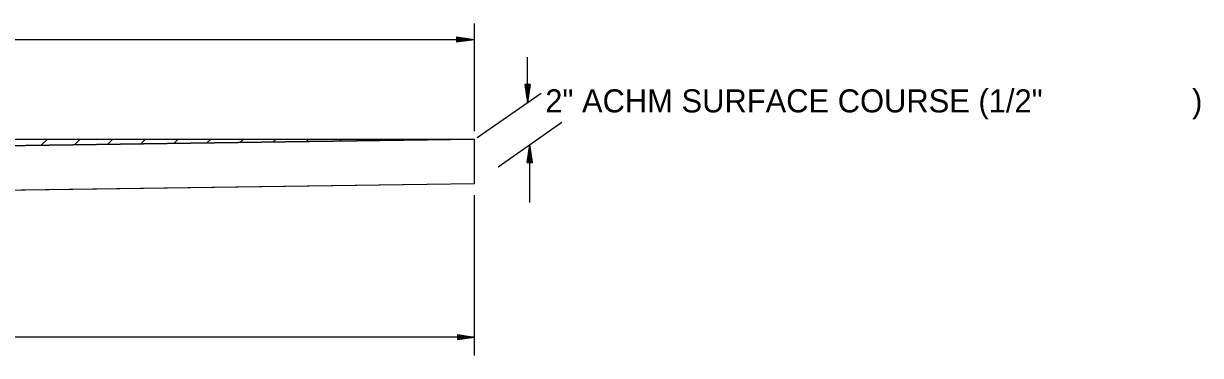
# Model space of a CAD drawing. Extents: x 1929624 to 1935547, y 596315 to 605721.
# Drawn here: x 1935241 to 1935546.7, y 602932.7 to 603019.1 of the extents above; entities that cross this region are included whole.
import ezdxf

# ---------------------------------------------------------------- set-up
doc = ezdxf.new("R2010")
doc.units = 0
doc.layers.add('Default', color=7, linetype='Continuous')

msp = doc.modelspace()

# ---------------------------------------------------------------- linework, layer by layer
at = {"layer": 'Default'}
for p, q in [((1935358.17, 602991.08), (1935358.17, 603019.07)), ((1935353.49, 603015.59), (1935358.17, 603014.92)), ((1935353.49, 603015.59), (1935353.49, 603014.26)), ((1935353.49, 603015.37), (1935356.61, 603014.92)), ((1935353.49, 603015.37), (1935357.26, 603014.92)), ((1934946.84, 603014.92), (1935358.16, 603014.92)), ((1935353.49, 603015.14), (1935355.05, 603014.92)), ((1935353.49, 603015.14), (1935355.73, 603014.92)), ((1935353.49, 603014.26), (1935358.17, 603014.92)), ((1935353.49, 603014.71), (1935355.05, 603014.92)), ((1935353.49, 603014.48), (1935356.61, 603014.92)), ((1935353.49, 603014.26), (1935357.26, 603014.92)), ((1935353.49, 603014.48), (1935355.73, 603014.92)), ((1935353.49, 603014.71), (1935354.17, 603014.92)), ((1935353.49, 603014.92), (1935354.17, 603014.92)), ((1935371.93, 602998.51), (1935371.93, 603010.28)), ((1935371.27, 603003.17), (1935371.93, 602998.51)), ((1935372.6, 603003.17), (1935371.27, 603003.17)), ((1935371.5, 603003.17), (1935371.93, 603000.07)), ((1935371.5, 603003.17), (1935371.93, 602999.4)), ((1935371.7, 603003.17), (1935371.93, 603001.63)), ((1935371.7, 603003.17), (1935371.93, 603000.96)), ((1935372.6, 603003.17), (1935371.93, 602998.51)), ((1935372.15, 603003.17), (1935371.93, 603001.63)), ((1935372.38, 603003.17), (1935371.93, 603000.07)), ((1935372.6, 603003.17), (1935371.93, 602999.4)), ((1935372.38, 603003.17), (1935371.93, 603000.96)), ((1935371.93, 603003.17), (1935371.93, 603002.51)), ((1935372.15, 603003.17), (1935371.93, 603002.51)), ((1935358.84, 602989.44), (1935375.48, 603000.96)), ((1935364.27, 602981.74), (1935380.81, 602993.4)), ((1934932.98, 602988.94), (1935358.17, 602988.97)), ((1934946.84, 602983.17), (1935358.17, 602988.97)), ((1935245.65, 602987.38), (1935247.22, 602988.96)), ((1935254.25, 602987.51), (1935255.71, 602988.96)), ((1935262.86, 602987.63), (1935264.2, 602988.96)), ((1935271.47, 602987.75), (1935272.68, 602988.96)), ((1935280.07, 602987.87), (1935281.17, 602988.97)), ((1935288.68, 602987.99), (1935289.65, 602988.97)), ((1935297.29, 602988.11), (1935298.14, 602988.97)), ((1935305.89, 602988.24), (1935306.63, 602988.97)), ((1935314.5, 602988.36), (1935315.11, 602988.97)), ((1935323.11, 602988.48), (1935323.6, 602988.97)), ((1935331.71, 602988.6), (1935332.08, 602988.97)), ((1935340.32, 602988.72), (1935340.57, 602988.97)), ((1935348.93, 602988.84), (1935349.06, 602988.97)), ((1935357.53, 602988.96), (1935357.54, 602988.97)), ((1935358.18, 602977.43), (1935358.17, 602988.97)), ((1935371.88, 602982.9), (1935372.54, 602987.57)), ((1935372.11, 602982.9), (1935372.54, 602986.9)), ((1935372.11, 602982.9), (1935372.54, 602986.01)), ((1935372.31, 602982.9), (1935372.54, 602985.34)), ((1935372.54, 602972.47), (1935372.54, 602987.57)), ((1935373.21, 602982.9), (1935372.54, 602987.57)), ((1935373.21, 602982.9), (1935372.54, 602986.9)), ((1935372.99, 602982.9), (1935372.54, 602986.01)), ((1935372.99, 602982.9), (1935372.54, 602985.34)), ((1935371.88, 602982.9), (1935373.21, 602982.9)), ((1935372.31, 602982.9), (1935372.54, 602984.45)), ((1935372.76, 602982.9), (1935372.54, 602984.45)), ((1935372.76, 602982.9), (1935372.54, 602983.8)), ((1935372.54, 602982.9), (1935372.54, 602983.8)), ((1934946.84, 602971.63), (1935358.18, 602977.43)), ((1935358.17, 602932.69), (1935358.17, 602974.44)), ((1935358.17, 602937.5), (1934946.84, 602937.5)), ((1935353.72, 602938.16), (1935358.17, 602937.5)), ((1935353.72, 602938.16), (1935357.49, 602937.5)), ((1935353.72, 602938.16), (1935353.72, 602936.83)), ((1935353.72, 602937.95), (1935356.61, 602937.5)), ((1935353.72, 602937.95), (1935355.96, 602937.5)), ((1935353.72, 602937.71), (1935355.07, 602937.5)), ((1935353.72, 602937.71), (1935354.4, 602937.5)), ((1935353.72, 602936.83), (1935358.17, 602937.5)), ((1935353.72, 602937.27), (1935355.07, 602937.5)), ((1935353.72, 602937.05), (1935356.61, 602937.5)), ((1935353.72, 602937.05), (1935357.49, 602937.5)), ((1935353.72, 602937.27), (1935355.96, 602937.5)), ((1935353.72, 602937.5), (1935354.4, 602937.5))]:
    msp.add_line(p, q, dxfattribs=at)
for points in [[(1934946.84, 602984.61), (1934946.84, 602983.17), (1935358.17, 602988.97), (1934946.84, 602988.93)], [(1934946.84, 602983.17), (1934946.84, 602971.63), (1935358.18, 602977.43), (1935358.17, 602988.97), (1934946.84, 602983.17)], [(1934946.84, 602983.17), (1934946.84, 602971.63), (1935358.18, 602977.43), (1935358.17, 602988.97), (1934946.84, 602983.17)]]:
    msp.add_lwpolyline(points, dxfattribs=at)

# ---------------------------------------------------------------- texts
for s, p in [('2" ACHM SURFACE COURSE (1/2"', (1935376.55, 602995.94)), (')', (1935544.55, 602995.94))]:
    msp.add_text(s, height=6, rotation=360, dxfattribs=at).set_placement(p)

doc.saveas('drawing.dxf')
